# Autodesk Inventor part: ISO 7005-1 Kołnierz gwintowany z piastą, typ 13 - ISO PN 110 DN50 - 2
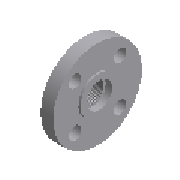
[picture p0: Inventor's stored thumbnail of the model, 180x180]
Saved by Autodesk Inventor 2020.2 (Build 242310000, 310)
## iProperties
Manager: www.cadconsulting.pl
Company: Fabian Stasiak CAD Consulting
IsCustomPart: 0
NAME: PIPING: ISO 7005-1 Hubbed Threaded Flange Type 13 - PN 110
DATA: <meta><inlinegroups number="1" deflen="1.8"></inlinegroups><connections number="2"></connections><angles><a>3.14159265358979</a></angles></meta>
Created: 2014-02
Part Number: ISO 7005-1 Kołnierz gwintowany z piastą, typ 13 - ISO PN 110 DN50 - 2
Material: Stal
Description: Kołnierze metalowe - Część 1: Kołnierze stalowe - Kołnierz gwintowany z piastą, typ 13 - ISO PN 110
Document SubType Name: Modeling
Standard: ISO 7005-1
Designer: F.Stasiak
Standard Revision: First edition 1992-04-15
Standards Organization: ISO
Language: pl-PL
Size Designation: DN50 - 2
Categories: <MemberInstance><Categories><Category DisplayName="Rury cienko- i grubościenne" InternalName="4347fa0f-2144-441d-94cd-e3e15c92b736" Mnemonic="TUBEANDPIPE"><Cate
Density: 1 g/cm^3
Appearance: Płyta
Catalog Web Link: www.expertbooks.pl
Author: F.Stasiak
Subject: Zbiór ćwiczeń. Autodesk Inventor 2020. Kurs Professional
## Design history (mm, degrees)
sketch "Sketch1"
  geometry: L1 (0, 0)-(37, 0) reference; L2 (0, 27.422)-(0, 46); L3 (0, 46)-(7, 46); L4 (7, 82.5)-(32.5, 82.5); L5 (0, 27.422)-(0, 0); L6 (7, 82.5)-(7, 46); L7 (32.5, 82.5)-(32.5, 42); L8 (32.5, 42)-(37, 42); L9 (37, 0)-(37, 32); L10 (37, 42)-(37, 32); L11 (29, 32)-(29, 28.328); L12 (29, 28.328)-(0, 27.422); L13 (29, 32)-(37, 32)
  constraints: 26 end point, 4 perpendicular, 3 parallel, 1 collinear, 1 horizontal
  dimensions: "d0" = 92 diameter of L3 L1 (= D1); "d1" = 165 diameter of L4 L1 (= D); "d2" = 84 diameter of L7.end L1 (= N2); "d3" = 7 distance between parallel lines of L2 L6 (= F2); "d9" = 64 diameter of L13 L1 (= V1); "d10" = 37 distance between parallel lines of L2 L10 (= H1); "d12" = 56.656 diameter of L11.end L1 (= MD); "d13" = 29 distance between parallel lines of L2 L11 (= T1); "d14" = 1.78991 deg angle of L1 L12; "d15" = 25.5 distance of L4.start L4.end (= C2)
revolve "Revolution1" stored, may be unused: angle "d11" = 90 deg
sketch "Sketch2"
  geometry: L1 (0, 0)-(0, 63.5); L2 (0, 0)-(24.3, 58.666); C1 r 46 at (0, 0) reference; C2 r 82.5 at (0, 0) reference; C3 r 9 at (24.3, 58.666); A1 r 63.5 centre (0, 0) between (0, 63.5) and (24.3, 58.666)
  constraints: 4 end point, 2 centre point, 2 coincident, 2 point on circle, 1 vertical
  dimensions: "d4" = 63.5 distance of L1.start L1.end (= 0.5 x K1); "d16" = 18 diameter of C3 (= L); "d17" = 22.5 deg angle of L2 L1 (computed from NU)
extrude "Extrusion1" cut sketch "Sketch2" distance "d5" = 25.5 (= C2); taper "d6" = 0 deg
pattern_circular "Circular Pattern1" dims angle "d8" = 360 deg
workaxis "Work Axis4"
workpoint "Work Point5"
workaxis "Work Axis5"
workpoint "Work Point6"
workaxis "Work Axis6"
workaxis "Work Axis7"
workpoint "Work Point7"
body "Solid1"
feature "Gwint1" dims "d122" = 10, "d123" = 0
other parameters: "C2" = 25.5 [user parameter; used in 2 equation terms], "D" = 165 [user parameter; used in 1 equation term], "K1" = 127 [user parameter; used in 1 equation term], "L" = 18 [user parameter; used in 1 equation term], "N2" = 84 [user parameter; used in 1 equation term], "D1" = 92 [user parameter; used in 1 equation term], "H1" = 37 [user parameter; used in 1 equation term], "F2" = 7 [user parameter; used in 1 equation term], "MD" = 56.656 [user parameter; used in 1 equation term], "T1" = 29 [user parameter; used in 1 equation term], "V1" = 64 [user parameter; used in 1 equation term], "Size_Designation" = 12.345 [user parameter]
